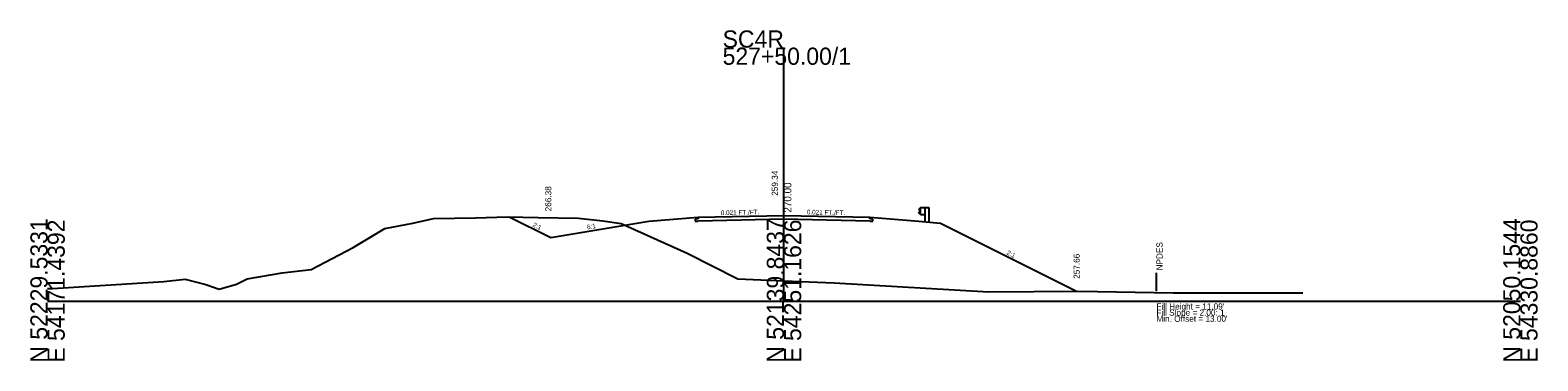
# Model space of a CAD drawing. Extents: x 9740 to 17409, y 8856 to 28416.
# Drawn here: x 10763 to 11008.7, y 28361.7 to 28415.5 of the extents above; entities that cross this region are included whole.
import ezdxf

# ---------------------------------------------------------------- set-up
doc = ezdxf.new("R2010")
doc.units = 0
for name, color, linetype in [('Level 10', 7, 'Continuous'), ('Level 11', 7, 'Continuous'), ('Level 12', 7, 'Continuous'), ('Level 24', 7, 'Continuous'), ('Level 32', 7, 'Continuous'), ('Level 33', 7, 'Continuous'), ('Level 50', 7, 'Continuous'), ('Level 55', 7, 'Continuous'), ('Level 59', 7, 'Continuous'), ('Level 6', 7, 'Continuous'), ('Level 60', 7, 'Continuous'), ('Level 63', 7, 'Continuous'), ('Level 7', 7, 'Continuous')]:
    doc.layers.add(name, color=color, linetype=linetype)

msp = doc.modelspace()

# ---------------------------------------------------------------- linework, layer by layer
at = {"layer": 'Level 11'}
for p, q in [((10871.85, 28384.79), (10871.35, 28384.78)), ((10871.35, 28384.78), (10871.35, 28384.44)), ((10871.35, 28384.44), (10871.85, 28384.45)), ((10871.85, 28385.09), (10871.85, 28384.79)), ((10899.85, 28384.79), (10899.85, 28385.09)), ((10900.35, 28384.78), (10899.85, 28384.79)), ((10899.85, 28384.45), (10900.35, 28384.44)), ((10900.35, 28384.44), (10900.35, 28384.78))]:
    msp.add_line(p, q, dxfattribs=at)
at = {"layer": 'Level 12'}
for p, q in [((10885.85, 28384.74), (10871.85, 28384.45)), ((10899.85, 28384.45), (10885.85, 28384.74))]:
    msp.add_line(p, q, dxfattribs=at)
at = {"layer": 'Level 24'}
for p, q in [((10908.12, 28386.6), (10907.85, 28386.4)), ((10907.85, 28386.4), (10907.85, 28386.35)), ((10907.85, 28386.35), (10908.12, 28386.15)), ((10908.12, 28385.51), (10908.12, 28386.67)), ((10908.12, 28386.67), (10908.79, 28386.67)), ((10908.79, 28386.67), (10908.79, 28384.34)), ((10908.79, 28386.67), (10909.46, 28386.67)), ((10909.46, 28386.67), (10909.46, 28384.29)), ((10907.85, 28385.83), (10908.12, 28386.03)), ((10907.85, 28385.78), (10907.85, 28385.83)), ((10908.12, 28385.58), (10907.85, 28385.78)), ((10908.12, 28385.51), (10908.79, 28385.51))]:
    msp.add_line(p, q, dxfattribs=at)
at = {"layer": 'Level 55'}
msp.add_line((10946.54, 28373.04), (10946.54, 28376.04), dxfattribs=at)
at = {"layer": 'Level 59'}
for p, q in [((10871.85, 28385.09), (10885.85, 28385.38)), ((10885.85, 28385.38), (10899.85, 28385.09))]:
    msp.add_line(p, q, dxfattribs=at)
at = {"layer": 'Level 6'}
for p, q in [((10863.85, 28384.42), (10871.85, 28385.09)), ((10899.85, 28385.09), (10907.85, 28384.42)), ((10907.85, 28384.42), (10911.35, 28384.13))]:
    msp.add_line(p, q, dxfattribs=at)
at = {"layer": 'Level 60'}
for p, q in [((10820.81, 28383.23), (10825.39, 28384.12)), ((10825.39, 28384.12), (10828.73, 28384.85)), ((10828.73, 28384.85), (10835.59, 28385)), ((10835.59, 28385), (10840.79, 28385.15)), ((10840.79, 28385.15), (10845.8, 28385.03)), ((10845.8, 28385.03), (10852.37, 28384.92)), ((10852.37, 28384.92), (10856.33, 28384.47)), ((10856.33, 28384.47), (10859.32, 28384.04)), ((10859.32, 28384.04), (10870.08, 28379.22)), ((10815.66, 28380.13), (10820.81, 28383.23)), ((10808.82, 28376.54), (10815.66, 28380.13)), ((10870.08, 28379.22), (10878.31, 28375.02)), ((10804.08, 28376.02), (10808.82, 28376.54)), ((10766.65, 28373.44), (10784.79, 28374.58)), ((10784.79, 28374.58), (10788.25, 28374.97)), ((10788.25, 28374.97), (10791.66, 28374.11)), ((10791.66, 28374.11), (10793.82, 28373.34)), ((10793.82, 28373.34), (10796.66, 28374.19)), ((10796.66, 28374.19), (10798.38, 28375.05)), ((10798.38, 28375.05), (10804.08, 28376.02)), ((10878.31, 28375.02), (10885.85, 28374.72)), ((10885.85, 28374.72), (10894.01, 28374.39)), ((10894.01, 28374.39), (10919.24, 28372.95)), ((10765.85, 28373.44), (10766.65, 28373.44)), ((10919.24, 28372.95), (10933.84, 28373.04)), ((10933.84, 28373.04), (10949.26, 28372.76)), ((10949.26, 28372.76), (10957.87, 28372.75)), ((10957.87, 28372.75), (10970.37, 28372.76))]:
    msp.add_line(p, q, dxfattribs=at)
at = {"layer": 'Level 63'}
for p, q in [((10885.85, 28371.38), (10885.85, 28412.7)), ((10765.85, 28371.38), (10885.85, 28371.38)), ((10885.85, 28371.38), (11005.85, 28371.38))]:
    msp.add_line(p, q, dxfattribs=at)
at = {"layer": 'Level 7'}
for p, q in [((10841.07, 28385.15), (10847.85, 28381.76)), ((10847.85, 28381.76), (10863.85, 28384.42)), ((10911.35, 28384.13), (10933.54, 28373.04))]:
    msp.add_line(p, q, dxfattribs=at)

# ---------------------------------------------------------------- texts
at = {"layer": 'Level 10'}
msp.add_text('259.34', height=1, rotation=90, dxfattribs=at).set_placement((10884.85, 28388.57))
at = {"layer": 'Level 32'}
for s, rotation, p in [('0.021 FT./FT.', 1.1916, (10875.56, 28385.42)), ('0.021 FT./FT.', 358.8084, (10889.57, 28385.55)), ('2:1', 333.435, (10844.82, 28383.59)), ('6:1', 9.4623, (10853.81, 28383.08)), ('2:1', 333.435, (10922.05, 28379.06))]:
    msp.add_text(s, height=0.75, rotation=rotation, dxfattribs=at).set_placement(p)
at = {"layer": 'Level 33'}
for s, p in [('266.38', (10847.94, 28386.03)), ('257.66', (10934.04, 28375.04))]:
    msp.add_text(s, height=1, rotation=90, dxfattribs=at).set_placement(p)
at = {"layer": 'Level 50'}
msp.add_text(' NPDES', height=1, rotation=90, dxfattribs=at).set_placement((10947.54, 28376.04))
for s, p in [("Fill Height = 11.09' ", (10946.54, 28370.04)), ('Fill Slope = 2.00: 1', (10946.54, 28369.04)), ("Min. Offset = 13.00' ", (10946.54, 28368.04))]:
    msp.add_text(s, height=1, dxfattribs=at).set_placement(p)
at = {"layer": 'Level 59'}
msp.add_text(' 270.00', height=1.2, rotation=90, dxfattribs=at).set_placement((10887.05, 28385.38))
at = {"layer": 'Level 63'}
for s, p in [('SC4R', (10875.85, 28412.7)), ('527+50.00/1', (10875.85, 28409.9))]:
    msp.add_text(s, height=2.8, dxfattribs=at).set_placement(p)
for s, p in [('N 52229.5331', (10765.85, 28361.38)), ('E 54171.4392', (10768.65, 28361.38)), ('N 52139.8437', (10885.85, 28361.38)), ('E 54251.1626', (10888.65, 28361.38)), ('N 52050.1544', (11005.85, 28361.38)), ('E 54330.8860', (11008.65, 28361.38))]:
    msp.add_text(s, height=2.8, rotation=90, dxfattribs=at).set_placement(p)

doc.saveas('drawing.dxf')
